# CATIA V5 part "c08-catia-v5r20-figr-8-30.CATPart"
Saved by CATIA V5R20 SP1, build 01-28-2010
Part number: Part1
Bounding box of the stored display mesh (mm): x -50 to 50, y -75 to 125, z 0 to 40
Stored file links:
  D:\v5_r20\psrt_files_downloaded\c08-catia-v5r20-prt\c08-catia-v5r20-figr-8-30.CATPart
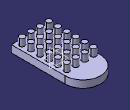
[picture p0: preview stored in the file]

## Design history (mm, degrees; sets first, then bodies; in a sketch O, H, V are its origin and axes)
Body1 (main body)
  Sketch1 on xy-plane, origin (0, 0, 0), H (1, 0, 0), V (0, 1, 0)
    line L1 (50, 75) -> (50, -75)
    line L2 (50, -75) -> (-50, -75)
    line L3 (-50, -75) -> (-50, 75)
    arc A1 centre (0, 75) radius 50 from (-50, 75) to (50, 75) cw
    point P5 (0, 75)
    axis line L4 (50, -75) -> (-50, 75)
    length L2 = 100
    distance P5 L2 = 150
    horizontal: L2 H
    vertical: L1 V, L3 V
    tangency: A1 L3, A1 L1
    midpoint: O L4
  Pad1: profile Sketch1, direction (0, 0, 1), length 20
  Sketch2 on face of Pad1, origin (0, 0, 20), H (1, 0, 0), V (0, 1, 0)
    circle A1 centre (35, -60) radius 7.5
    point P1 (35, -60)
    reference projected line E1 (-50, -75) -> (50, -75) from edge [face of Pad1 | face of Pad1]
    reference projected line E2 (50, -75) -> (50, 75) from edge [face of Pad1 | face of Pad1]
    distance P1 E1 = 15
    distance P1 E2 = 15
    radius A1 = 7.5
  Pad2: profile Sketch2, direction (0, 0, 1), length 20
  RectPattern1: of Pad2, direction 1 instances 4, spacing 25, along edge [face of Pad1 | face of Pad1] reversed, direction 2 instances 6, spacing 25, along edge [face of Pad1 | face of Pad1]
